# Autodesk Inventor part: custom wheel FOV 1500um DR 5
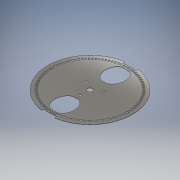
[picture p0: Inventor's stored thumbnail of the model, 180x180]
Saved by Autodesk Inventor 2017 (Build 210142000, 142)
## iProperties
Created: 2016-09
Part Number: custom wheel FOV 1500um DR 5
Material: Generic
Document SubType Name: Modeling
Designer: Radek
Density: 1 g/cm^3
Appearance: Mirror
Author: Radek
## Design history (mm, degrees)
workplane "Work Plane1"
sketch "Sketch1"
  geometry: L1 (-46.781, 4.422)-(-44.253, 4.183) reference; L2 (-44.362, 2.791)-(-46.897, 2.951) reference; L3 (-46.411, 7.351)-(-43.903, 6.954) reference; L4 (-44.099, 5.571)-(-46.619, 5.889) reference; L5 (-45.858, 10.251)-(-43.38, 9.696) reference; L6 (-43.663, 8.329)-(-46.158, 8.805) reference; L7 (-45.124, 13.11)-(-42.685, 12.401) reference; L8 (-43.054, 11.054)-(-45.514, 11.686) reference; L9 (-44.212, 15.917)-(-41.822, 15.057) reference; L10 (-42.274, 13.736)-(-44.69, 14.521) reference; L11 (-43.125, 18.662)-(-40.794, 17.653) reference; L12 (-41.329, 16.363)-(-43.69, 17.298) reference; L13 (-41.868, 21.333)-(-39.605, 20.18) reference; L14 (-40.22, 18.926)-(-42.518, 20.007) reference; L15 (-40.446, 23.92)-(-38.26, 22.627) reference; L16 (-38.952, 21.414)-(-41.178, 22.638) reference; L17 (-38.865, 26.412)-(-36.764, 24.985) reference; L18 (-37.53, 23.818)-(-39.675, 25.179) reference; L19 (-37.129, 28.801)-(-35.122, 27.244) reference; L20 (-35.961, 26.127)-(-38.016, 27.62) reference; L21 (-35.248, 31.075)-(-33.342, 29.395) reference; L22 (-34.249, 28.333)-(-36.206, 29.953) reference; L23 (-33.227, 33.227)-(-31.431, 31.431) reference; L24 (-32.403, 30.428)-(-34.254, 32.167) reference; L25 (-31.075, 35.248)-(-29.395, 33.342) reference; L26 (-30.428, 32.403)-(-32.167, 34.254) reference; L27 (-28.801, 37.129)-(-27.244, 35.122) reference; L28 (-28.333, 34.249)-(-29.953, 36.206) reference; L29 (-26.412, 38.865)-(-24.985, 36.764) reference; L30 (-26.127, 35.961)-(-27.62, 38.016) reference; L31 (-23.92, 40.446)-(-22.627, 38.26) reference; L32 (-23.818, 37.53)-(-25.179, 39.675) reference; L33 (-21.333, 41.868)-(-20.18, 39.605) reference; L34 (-21.414, 38.952)-(-22.638, 41.178) reference; L35 (-18.662, 43.125)-(-17.653, 40.794) reference; L36 (-18.926, 40.22)-(-20.007, 42.518) reference; L37 (-15.917, 44.212)-(-15.057, 41.822) reference; L38 (-16.363, 41.329)-(-17.298, 43.69) reference; L39 (-13.11, 45.124)-(-12.401, 42.685) reference; L40 (-13.736, 42.274)-(-14.521, 44.69) reference; L41 (-10.251, 45.858)-(-9.696, 43.38) reference; L42 (-11.054, 43.054)-(-11.686, 45.514) reference; L43 (-7.351, 46.411)-(-6.954, 43.903) reference; L44 (-8.329, 43.663)-(-8.805, 46.158) reference; L45 (-4.422, 46.781)-(-4.183, 44.253) reference; L46 (-5.571, 44.099)-(-5.889, 46.619) reference; L47 (-1.476, 46.967)-(-1.396, 44.428) reference; L48 (-2.791, 44.362)-(-2.951, 46.897) reference; L49 (1.476, 46.967)-(1.396, 44.428) reference; L50 (0, 44.45)-(0, 46.99) reference; L51 (4.422, 46.781)-(4.183, 44.253) reference; L52 (2.791, 44.362)-(2.951, 46.897) reference; L53 (7.351, 46.411)-(6.954, 43.903) reference; L54 (5.571, 44.099)-(5.889, 46.619) reference; L55 (10.251, 45.858)-(9.696, 43.38) reference; L56 (8.329, 43.663)-(8.805, 46.158) reference; L57 (13.11, 45.124)-(12.401, 42.685) reference; L58 (11.054, 43.054)-(11.686, 45.514) reference; L59 (15.917, 44.212)-(15.057, 41.822) reference; L60 (13.736, 42.274)-(14.521, 44.69) reference; L61 (18.662, 43.125)-(17.653, 40.794) reference; L62 (16.363, 41.329)-(17.298, 43.69) reference; L63 (21.333, 41.868)-(20.18, 39.605) reference; L64 (18.926, 40.22)-(20.007, 42.518) reference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; C1 r 50.8 at (0, 0) reference; C2 r 2.984 at (0, 0) reference; C3 r 1.524 at (0, 6.553) reference; C4 r 1.524 at (10.339, 5.969) reference; C5 r 2.984 at (0, 0) reference; C6 r 1.524 at (0, -11.938) reference; C7 r 1.524 at (-5.675, -3.277) reference; C8 r 1.524 at (-10.339, 5.969) reference; C9 r 1.524 at (5.675, -3.277) reference; C10 r 50.8 at (0, 0) reference; C11 r 1.524 at (-5.675, -3.277) reference; C12 r 1.524 at (-10.339, 5.969) reference; C13 r 1.524 at (0, 6.553) reference; C14 r 1.524 at (10.339, 5.969) reference; C15 r 1.524 at (5.675, -3.277) reference; C16 r 1.524 at (0, -11.938) reference; C17 r 2.984 at (0, 0) reference; A1 r 17.081 centre (0, 0) between (0, -17.081) and (17.081, 0) reference; A2 r 17.081 centre (0, 0) between (0, 17.081) and (-17.081, 0) reference; A3 r 43.18 centre (0, 0) between (0, 43.18) and (-43.18, 0) reference; A4 r 43.18 centre (0, 0) between (0, -43.18) and (43.18, 0) reference; A5 r 44.45 centre (0, 0) between (-44.253, 4.183) and (-44.362, 2.791) reference; A6 r 46.99 centre (0, 0) between (-46.781, 4.422) and (-46.897, 2.951) reference; A7 r 44.45 centre (0, 0) between (-43.903, 6.954) and (-44.099, 5.571) reference; A8 r 46.99 centre (0, 0) between (-46.411, 7.351) and (-46.619, 5.889) reference; A9 r 44.45 centre (0, 0) between (-43.38, 9.696) and (-43.663, 8.329) reference; A10 r 46.99 centre (0, 0) between (-45.858, 10.251) and (-46.158, 8.805) reference; A11 r 44.45 centre (0, 0) between (-42.685, 12.401) and (-43.054, 11.054) reference; A12 r 46.99 centre (0, 0) between (-45.124, 13.11) and (-45.514, 11.686) reference; A13 r 44.45 centre (0, 0) between (-41.822, 15.057) and (-42.274, 13.736) reference; A14 r 46.99 centre (0, 0) between (-44.212, 15.917) and (-44.69, 14.521) reference; A15 r 44.45 centre (0, 0) between (-40.794, 17.653) and (-41.329, 16.363) reference; A16 r 46.99 centre (0, 0) between (-43.125, 18.662) and (-43.69, 17.298) reference; A17 r 44.45 centre (0, 0) between (-39.605, 20.18) and (-40.22, 18.926) reference; A18 r 46.99 centre (0, 0) between (-41.868, 21.333) and (-42.518, 20.007) reference; A19 r 44.45 centre (0, 0) between (-38.26, 22.627) and (-38.952, 21.414) reference; A20 r 46.99 centre (0, 0) between (-40.446, 23.92) and (-41.178, 22.638) reference; A21 r 44.45 centre (0, 0) between (-36.764, 24.985) and (-37.53, 23.818) reference; A22 r 46.99 centre (0, 0) between (-38.865, 26.412) and (-39.675, 25.179) reference; A23 r 44.45 centre (0, 0) between (-35.122, 27.244) and (-35.961, 26.127) reference; A24 r 46.99 centre (0, 0) between (-37.129, 28.801) and (-38.016, 27.62) reference; A25 r 44.45 centre (0, 0) between (-33.342, 29.395) and (-34.249, 28.333) reference; A26 r 46.99 centre (0, 0) between (-35.248, 31.075) and (-36.206, 29.953) reference; A27 r 44.45 centre (0, 0) between (-31.431, 31.431) and (-32.403, 30.428) reference; A28 r 46.99 centre (0, 0) between (-33.227, 33.227) and (-34.254, 32.167) reference; A29 r 44.45 centre (0, 0) between (-29.395, 33.342) and (-30.428, 32.403) reference; A30 r 46.99 centre (0, 0) between (-31.075, 35.248) and (-32.167, 34.254) reference; A31 r 44.45 centre (0, 0) between (-27.244, 35.122) and (-28.333, 34.249) reference; A32 r 46.99 centre (0, 0) between (-28.801, 37.129) and (-29.953, 36.206) reference; A33 r 44.45 centre (0, 0) between (-24.985, 36.764) and (-26.127, 35.961) reference; A34 r 46.99 centre (0, 0) between (-26.412, 38.865) and (-27.62, 38.016) reference; A35 r 44.45 centre (0, 0) between (-22.627, 38.26) and (-23.818, 37.53) reference; A36 r 46.99 centre (0, 0) between (-23.92, 40.446) and (-25.179, 39.675) reference; A37 r 44.45 centre (0, 0) between (-20.18, 39.605) and (-21.414, 38.952) reference; A38 r 46.99 centre (0, 0) between (-21.333, 41.868) and (-22.638, 41.178) reference; A39 r 44.45 centre (0, 0) between (-17.653, 40.794) and (-18.926, 40.22) reference; A40 r 46.99 centre (0, 0) between (-18.662, 43.125) and (-20.007, 42.518) reference; A41 r 44.45 centre (0, 0) between (-15.057, 41.822) and (-16.363, 41.329) reference; A42 r 46.99 centre (0, 0) between (-15.917, 44.212) and (-17.298, 43.69) reference; A43 r 44.45 centre (0, 0) between (-12.401, 42.685) and (-13.736, 42.274) reference; A44 r 46.99 centre (0, 0) between (-13.11, 45.124) and (-14.521, 44.69) reference; A45 r 44.45 centre (0, 0) between (-9.696, 43.38) and (-11.054, 43.054) reference; A46 r 46.99 centre (0, 0) between (-10.251, 45.858) and (-11.686, 45.514) reference; A47 r 44.45 centre (0, 0) between (-6.954, 43.903) and (-8.329, 43.663) reference; A48 r 46.99 centre (0, 0) between (-7.351, 46.411) and (-8.805, 46.158) reference; A49 r 44.45 centre (0, 0) between (-4.183, 44.253) and (-5.571, 44.099) reference; A50 r 46.99 centre (0, 0) between (-4.422, 46.781) and (-5.889, 46.619) reference; A51 r 44.45 centre (0, 0) between (-1.396, 44.428) and (-2.791, 44.362) reference; A52 r 46.99 centre (0, 0) between (-1.476, 46.967) and (-2.951, 46.897) reference; A53 r 44.45 centre (0, 0) between (1.396, 44.428) and (0, 44.45) reference; A54 r 46.99 centre (0, 0) between (1.476, 46.967) and (0, 46.99) reference; A55 r 44.45 centre (0, 0) between (4.183, 44.253) and (2.791, 44.362) reference; A56 r 46.99 centre (0, 0) between (4.422, 46.781) and (2.951, 46.897) reference; A57 r 44.45 centre (0, 0) between (6.954, 43.903) and (5.571, 44.099) reference; A58 r 46.99 centre (0, 0) between (7.351, 46.411) and (5.889, 46.619) reference; A59 r 44.45 centre (0, 0) between (9.696, 43.38) and (8.329, 43.663) reference; A60 r 46.99 centre (0, 0) between (10.251, 45.858) and (8.805, 46.158) reference; A61 r 44.45 centre (0, 0) between (12.401, 42.685) and (11.054, 43.054) reference; A62 r 46.99 centre (0, 0) between (13.11, 45.124) and (11.686, 45.514) reference; A63 r 44.45 centre (0, 0) between (15.057, 41.822) and (13.736, 42.274) reference; A64 r 46.99 centre (0, 0) between (15.917, 44.212) and (14.521, 44.69) reference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; 1 further point
  constraints: 8 end point, 2 collinear, 1 parallel
extrude "Extrusion2" new body sketch "Sketch1" distance "d2" = 0.3; taper "d3" = 0 deg
sketch "Sketch2"
  geometry: L1 (-46.781, 4.422)-(-44.253, 4.183) reference; L2 (-44.362, 2.791)-(-46.897, 2.951) reference; L3 (-46.411, 7.351)-(-43.903, 6.954) reference; L4 (-44.099, 5.571)-(-46.619, 5.889) reference; L5 (-45.858, 10.251)-(-43.38, 9.696) reference; L6 (-43.663, 8.329)-(-46.158, 8.805) reference; L7 (-45.124, 13.11)-(-42.685, 12.401) reference; L8 (-43.054, 11.054)-(-45.514, 11.686) reference; L9 (-44.212, 15.917)-(-41.822, 15.057) reference; L10 (-42.274, 13.736)-(-44.69, 14.521) reference; L11 (-43.125, 18.662)-(-40.794, 17.653) reference; L12 (-41.329, 16.363)-(-43.69, 17.298) reference; L13 (-41.868, 21.333)-(-39.605, 20.18) reference; L14 (-40.22, 18.926)-(-42.518, 20.007) reference; L15 (-40.446, 23.92)-(-38.26, 22.627) reference; L16 (-38.952, 21.414)-(-41.178, 22.638) reference; L17 (-38.865, 26.412)-(-36.764, 24.985) reference; L18 (-37.53, 23.818)-(-39.675, 25.179) reference; L19 (-37.129, 28.801)-(-35.122, 27.244) reference; L20 (-35.961, 26.127)-(-38.016, 27.62) reference; L21 (-35.248, 31.075)-(-33.342, 29.395) reference; L22 (-34.249, 28.333)-(-36.206, 29.953) reference; L23 (-33.227, 33.227)-(-31.431, 31.431) reference; L24 (-32.403, 30.428)-(-34.254, 32.167) reference; L25 (-31.075, 35.248)-(-29.395, 33.342) reference; L26 (-30.428, 32.403)-(-32.167, 34.254) reference; L27 (-28.801, 37.129)-(-27.244, 35.122) reference; L28 (-28.333, 34.249)-(-29.953, 36.206) reference; L29 (-26.412, 38.865)-(-24.985, 36.764) reference; L30 (-26.127, 35.961)-(-27.62, 38.016) reference; L31 (-23.92, 40.446)-(-22.627, 38.26) reference; L32 (-23.818, 37.53)-(-25.179, 39.675) reference; L33 (-21.333, 41.868)-(-20.18, 39.605) reference; L34 (-21.414, 38.952)-(-22.638, 41.178) reference; L35 (-18.662, 43.125)-(-17.653, 40.794) reference; L36 (-18.926, 40.22)-(-20.007, 42.518) reference; L37 (-15.917, 44.212)-(-15.057, 41.822) reference; L38 (-16.363, 41.329)-(-17.298, 43.69) reference; L39 (-13.11, 45.124)-(-12.401, 42.685) reference; L40 (-13.736, 42.274)-(-14.521, 44.69) reference; L41 (-10.251, 45.858)-(-9.696, 43.38) reference; L42 (-11.054, 43.054)-(-11.686, 45.514) reference; L43 (-7.351, 46.411)-(-6.954, 43.903) reference; L44 (-8.329, 43.663)-(-8.805, 46.158) reference; L45 (-4.422, 46.781)-(-4.183, 44.253) reference; L46 (-5.571, 44.099)-(-5.889, 46.619) reference; L47 (-1.476, 46.967)-(-1.396, 44.428) reference; L48 (-2.791, 44.362)-(-2.951, 46.897) reference; L49 (1.476, 46.967)-(1.396, 44.428) reference; L50 (0, 44.45)-(0, 46.99) reference; L51 (4.422, 46.781)-(4.183, 44.253) reference; L52 (2.791, 44.362)-(2.951, 46.897) reference; L53 (7.351, 46.411)-(6.954, 43.903) reference; L54 (5.571, 44.099)-(5.889, 46.619) reference; L55 (10.251, 45.858)-(9.696, 43.38) reference; L56 (8.329, 43.663)-(8.805, 46.158) reference; L57 (13.11, 45.124)-(12.401, 42.685) reference; L58 (11.054, 43.054)-(11.686, 45.514) reference; L59 (15.917, 44.212)-(15.057, 41.822) reference; L60 (13.736, 42.274)-(14.521, 44.69) reference; L61 (18.662, 43.125)-(17.653, 40.794) reference; L62 (16.363, 41.329)-(17.298, 43.69) reference; L63 (21.333, 41.868)-(20.18, 39.605) reference; L64 (18.926, 40.22)-(20.007, 42.518) reference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; C1 r 50.8 at (0, 0) reference; C2 r 1.524 at (-5.675, -3.277) reference; C3 r 1.524 at (-10.339, 5.969) reference; C4 r 1.524 at (0, 6.553) reference; C5 r 1.524 at (10.339, 5.969) reference; C6 r 1.524 at (5.675, -3.277) reference; C7 r 1.524 at (0, -11.938) reference; C8 r 2.984 at (0, 0) reference; A1 r 44.45 centre (0, 0) between (-44.253, 4.183) and (-44.362, 2.791) reference; A2 r 46.99 centre (0, 0) between (-46.781, 4.422) and (-46.897, 2.951) reference; A3 r 44.45 centre (0, 0) between (-43.903, 6.954) and (-44.099, 5.571) reference; A4 r 46.99 centre (0, 0) between (-46.411, 7.351) and (-46.619, 5.889) reference; A5 r 44.45 centre (0, 0) between (-43.38, 9.696) and (-43.663, 8.329) reference; A6 r 46.99 centre (0, 0) between (-45.858, 10.251) and (-46.158, 8.805) reference; A7 r 44.45 centre (0, 0) between (-42.685, 12.401) and (-43.054, 11.054) reference; A8 r 46.99 centre (0, 0) between (-45.124, 13.11) and (-45.514, 11.686) reference; A9 r 44.45 centre (0, 0) between (-41.822, 15.057) and (-42.274, 13.736) reference; A10 r 46.99 centre (0, 0) between (-44.212, 15.917) and (-44.69, 14.521) reference; A11 r 44.45 centre (0, 0) between (-40.794, 17.653) and (-41.329, 16.363) reference; A12 r 46.99 centre (0, 0) between (-43.125, 18.662) and (-43.69, 17.298) reference; A13 r 44.45 centre (0, 0) between (-39.605, 20.18) and (-40.22, 18.926) reference; A14 r 46.99 centre (0, 0) between (-41.868, 21.333) and (-42.518, 20.007) reference; A15 r 44.45 centre (0, 0) between (-38.26, 22.627) and (-38.952, 21.414) reference; A16 r 46.99 centre (0, 0) between (-40.446, 23.92) and (-41.178, 22.638) reference; A17 r 44.45 centre (0, 0) between (-36.764, 24.985) and (-37.53, 23.818) reference; A18 r 46.99 centre (0, 0) between (-38.865, 26.412) and (-39.675, 25.179) reference; A19 r 44.45 centre (0, 0) between (-35.122, 27.244) and (-35.961, 26.127) reference; A20 r 46.99 centre (0, 0) between (-37.129, 28.801) and (-38.016, 27.62) reference; A21 r 44.45 centre (0, 0) between (-33.342, 29.395) and (-34.249, 28.333) reference; A22 r 46.99 centre (0, 0) between (-35.248, 31.075) and (-36.206, 29.953) reference; A23 r 44.45 centre (0, 0) between (-31.431, 31.431) and (-32.403, 30.428) reference; A24 r 46.99 centre (0, 0) between (-33.227, 33.227) and (-34.254, 32.167) reference; A25 r 44.45 centre (0, 0) between (-29.395, 33.342) and (-30.428, 32.403) reference; A26 r 46.99 centre (0, 0) between (-31.075, 35.248) and (-32.167, 34.254) reference; A27 r 44.45 centre (0, 0) between (-27.244, 35.122) and (-28.333, 34.249) reference; A28 r 46.99 centre (0, 0) between (-28.801, 37.129) and (-29.953, 36.206) reference; A29 r 44.45 centre (0, 0) between (-24.985, 36.764) and (-26.127, 35.961) reference; A30 r 46.99 centre (0, 0) between (-26.412, 38.865) and (-27.62, 38.016) reference; A31 r 44.45 centre (0, 0) between (-22.627, 38.26) and (-23.818, 37.53) reference; A32 r 46.99 centre (0, 0) between (-23.92, 40.446) and (-25.179, 39.675) reference; A33 r 44.45 centre (0, 0) between (-20.18, 39.605) and (-21.414, 38.952) reference; A34 r 46.99 centre (0, 0) between (-21.333, 41.868) and (-22.638, 41.178) reference; A35 r 44.45 centre (0, 0) between (-17.653, 40.794) and (-18.926, 40.22) reference; A36 r 46.99 centre (0, 0) between (-18.662, 43.125) and (-20.007, 42.518) reference; A37 r 44.45 centre (0, 0) between (-15.057, 41.822) and (-16.363, 41.329) reference; A38 r 46.99 centre (0, 0) between (-15.917, 44.212) and (-17.298, 43.69) reference; A39 r 44.45 centre (0, 0) between (-12.401, 42.685) and (-13.736, 42.274) reference; A40 r 46.99 centre (0, 0) between (-13.11, 45.124) and (-14.521, 44.69) reference; A41 r 44.45 centre (0, 0) between (-9.696, 43.38) and (-11.054, 43.054) reference; A42 r 46.99 centre (0, 0) between (-10.251, 45.858) and (-11.686, 45.514) reference; A43 r 44.45 centre (0, 0) between (-6.954, 43.903) and (-8.329, 43.663) reference; A44 r 46.99 centre (0, 0) between (-7.351, 46.411) and (-8.805, 46.158) reference; A45 r 44.45 centre (0, 0) between (-4.183, 44.253) and (-5.571, 44.099) reference; A46 r 46.99 centre (0, 0) between (-4.422, 46.781) and (-5.889, 46.619) reference; A47 r 44.45 centre (0, 0) between (-1.396, 44.428) and (-2.791, 44.362) reference; A48 r 46.99 centre (0, 0) between (-1.476, 46.967) and (-2.951, 46.897) reference; A49 r 44.45 centre (0, 0) between (1.396, 44.428) and (0, 44.45) reference; A50 r 46.99 centre (0, 0) between (1.476, 46.967) and (0, 46.99) reference; A51 r 44.45 centre (0, 0) between (4.183, 44.253) and (2.791, 44.362) reference; A52 r 46.99 centre (0, 0) between (4.422, 46.781) and (2.951, 46.897) reference; A53 r 44.45 centre (0, 0) between (6.954, 43.903) and (5.571, 44.099) reference; A54 r 46.99 centre (0, 0) between (7.351, 46.411) and (5.889, 46.619) reference; A55 r 44.45 centre (0, 0) between (9.696, 43.38) and (8.329, 43.663) reference; A56 r 46.99 centre (0, 0) between (10.251, 45.858) and (8.805, 46.158) reference; A57 r 44.45 centre (0, 0) between (12.401, 42.685) and (11.054, 43.054) reference; A58 r 46.99 centre (0, 0) between (13.11, 45.124) and (11.686, 45.514) reference; A59 r 44.45 centre (0, 0) between (15.057, 41.822) and (13.736, 42.274) reference; A60 r 46.99 centre (0, 0) between (15.917, 44.212) and (14.521, 44.69) reference; A61 r 44.45 centre (0, 0) between (17.653, 40.794) and (16.363, 41.329) reference; A62 r 46.99 centre (0, 0) between (18.662, 43.125) and (17.298, 43.69) reference; A63 r 44.45 centre (0, 0) between (20.18, 39.605) and (18.926, 40.22) reference; A64 r 46.99 centre (0, 0) between (21.333, 41.868) and (20.007, 42.518) reference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; 1 further point
  constraints: 8 end point, 1 collinear
extrude "Extrusion3" cut sketch "Sketch2" stored distance "d4" = 0.254; taper "d5" = 0 deg
sketch "Sketch3" dims "d20" = 9.26667 (= 0.5 x holediameter), "d21" = 13.10505 (= 1.41421 x d20)
  geometry: L1 (-10.339, 5.969)-(10.339, 5.969); L2 (0, 0)-(50.8, 0); L3 (0, 44.45)-(0, 46.99) reference; L4 (0, 0)-(0, 50.8); L5 (0, 30)-(0, 16.895); L6 (0, 50.165)-(0, 48.26) reference; L7 (-48.26, 0)-(-50.165, 0) reference; L8 (0, 0)-(13.619, 31.718); L9 (0, 50.8)-(0, 50.165); L10 (1.263, 16.848)-(3.221, 42.985); L11 (-1.263, 16.848)-(-3.221, 42.985); C1 r 2.984 at (0, 0) reference; C2 r 15.25 at (0, 0); C3 r 1.524 at (-10.339, 5.969) reference; C4 r 1.524 at (0, -11.938) reference; C5 r 1.524 at (10.339, 5.969) reference; C6 r 1.524 at (-5.675, -3.277) reference; C7 r 1.524 at (5.675, -3.277) reference; A1 r 50.8 centre (0, 0) between (50.8, 0) and (0, 50.8) reference; A2 r 48.26 centre (0, 0) between (0, 48.26) and (-48.26, 0) reference; A3 r 50.165 centre (0, 0) between (0, 50.165) and (-50.165, 0) reference; A4 r 50.165 centre (0, 0) between (-20.154, -45.939) and (22.037, -45.066); A5 r 48.26 centre (0, 0) between (-19.033, -44.348) and (20.956, -43.472); 3 further points; 3 other entities
  constraints: 16 end point, 8 point on circle, 3 centre point, 3 coincident, 2 midpoint, 2 vertical, 1 collinear, 1 horizontal, 1 parallel, 1 point on line, 1 vertical alignment, 19 other
  dimensions: "d9" = 30.5 diameter of C2; "d18" = 0 distance between parallel lines of L4 L5; "d19" = 30 distance of point (0, 0) L5.start (= offaxis); "d24" = 0.748 dimension on point (0, 0) L5.start point (-2.242, 29.916) (= 0.5 x angle); "d28" = 0.748 dimension on point (0, 0) point (2.242, 29.916) L5.start (= 0.5 x angle); "d32" = 0.635 distance of L4.end L6.start (derived)
extrude "Extrusion7" cut sketch "Sketch3" stored distance "d40" = 10; taper "d41" = 0 deg
sketch "Sketch4"
  geometry: L1 (-3.221, 42.985)-(-1.263, 16.848) reference; L2 (1.263, 16.848)-(3.221, 42.985) reference; L3 (3.221, 42.985)-(1.263, 16.848) reference; L4 (-1.263, 16.848)-(-3.221, 42.985) reference; L5 (-1.263, 16.848)-(-3.221, 42.985); L6 (1.263, 16.848)-(3.221, 42.985); C1 r 2.984 at (0, 0) reference; C2 r 50.8 at (0, 0) reference; A1 r 16.895 centre (0, 0) between (1.263, 16.848) and (-1.263, 16.848); A2 r 43.105 centre (0, 0) between (3.221, 42.985) and (-3.221, 42.985); 3 further points; 2 other entities
  constraints: 4 end point, 4 point on circle, 2 centre point, 2 coincident, 2 collinear, 2 other
extrude "Extrusion8" cut sketch "Sketch4" stored distance "d42" = 10; taper "d43" = 0 deg
sketch "Sketch5"
  geometry: L1 (0, 0)-(-7.947, 50.175); L2 (0, 0)-(7.947, 50.175); L3 (7.524, 47.508)-(7.837, 49.483); L4 (-7.524, 47.508)-(-7.837, 49.483); L5 (6.954, 43.903)-(7.351, 46.411) reference; L6 (4.422, 46.781)-(4.183, 44.253) reference; L7 (7.351, 46.411)-(6.954, 43.903) reference; C1 r 2.984 at (0, 0) reference; A1 r 50.8 centre (0, 0) between (-7.947, 50.175) and (7.947, 50.175) reference; A2 r 16.895 centre (0, 0) between (1.263, 16.848) and (-1.263, 16.848) reference; A3 r 43.105 centre (0, 0) between (3.221, 42.985) and (-3.221, 42.985) reference; A4 r 48.1 centre (0, 0) between (7.524, 47.508) and (-7.524, 47.508); A5 r 50.1 centre (0, 0) between (7.837, 49.483) and (-7.837, 49.483); 4 further points; 2 other entities
  constraints: 8 end point, 6 point on circle, 3 point on line, 2 centre point, 2 coincident, 2 collinear, 1 midpoint, 8 other
  dimensions: "d44" = 0.7 radial gap between concentric circles of A1 A5; "d45" = 2 radial gap between concentric circles of A5 A4; "d53" = 18 deg angle of L1 L2
extrude "Extrusion9" cut sketch "Sketch5" stored distance "d46" = 10; taper "d47" = 0 deg
pattern_circular "Circular Pattern3" dims angle "d49" = 360 deg
sketch "Sketch6"
  geometry: L1 (16.895, 0)-(16.848, 0) reference; L2 (42.985, 0)-(43.105, 0) reference; L3 (16.848, -0.3)-(16.895, -0.3) reference; L4 (43.105, -0.3)-(42.985, -0.3) reference; L5 (-50.8, 0)-(50.8, 0) reference; L6 (-50.8, -0.3)-(50.8, -0.3) reference; L7 (16.895, 0)-(43.105, 0); L8 (16.895, -0.3)-(43.105, -0.3); L9 (30, -0.3)-(30, 0); L10 (30, -0.15)-(32.935, -3.085); 1 further point
  constraints: 8 end point, 3 midpoint, 1 collinear, 1 parallel
  dimensions: "d51" = 135 deg angle of L10 L9
workaxis "Work Axis1"
workplane "Work Plane3"
  workplane "Work Plane2"
sketch "Sketch7"
  geometry: L1 (0, -11.938)-(-10.339, 5.969); C1 r 1.524 at (0, -11.938) reference; C2 r 1.524 at (-10.339, 5.969) reference; C3 r 2.984 at (0, 0) reference; C4 r 10.414 at (0, 0); 2 further points
  constraints: 2 end point, 1 centre point, 1 coincident, 1 tangent, 1 other
extrude "Extrusion11" cut sketch "Sketch7" stored distance "d57" = 10; taper "d58" = 0 deg
sketch "Sketch8"
  geometry: L1 (7.524, -47.508)-(7.837, -49.483) reference; L2 (-7.837, -49.483)-(-7.524, -47.508) reference; L3 (7.837, 49.483)-(7.524, 47.508) reference; L4 (-7.524, 47.508)-(-7.837, 49.483) reference; L5 (-46.967, -1.476)-(-44.428, -1.396) reference; L6 (-44.428, -1.396)-(-44.362, -2.791) reference; L7 (-44.362, -2.791)-(-46.897, -2.951) reference; L8 (-46.897, -2.951)-(-46.967, -1.476) reference; L9 (-46.781, -4.422)-(-44.253, -4.183) reference; L10 (-44.253, -4.183)-(-44.099, -5.571) reference; L11 (-44.099, -5.571)-(-46.619, -5.889) reference; L12 (-46.619, -5.889)-(-46.781, -4.422) reference; L13 (-46.411, -7.351)-(-43.903, -6.954) reference; L14 (-43.903, -6.954)-(-43.663, -8.329) reference; L15 (-43.663, -8.329)-(-46.158, -8.805) reference; L16 (-46.158, -8.805)-(-46.411, -7.351) reference; L17 (-45.858, -10.251)-(-43.38, -9.696) reference; L18 (-43.38, -9.696)-(-43.054, -11.054) reference; L19 (-43.054, -11.054)-(-45.514, -11.686) reference; L20 (-45.514, -11.686)-(-45.858, -10.251) reference; L21 (-45.124, -13.11)-(-42.685, -12.401) reference; L22 (-42.685, -12.401)-(-42.274, -13.736) reference; L23 (-42.274, -13.736)-(-44.69, -14.521) reference; L24 (-44.69, -14.521)-(-45.124, -13.11) reference; L25 (-44.212, -15.917)-(-41.822, -15.057) reference; L26 (-41.822, -15.057)-(-41.329, -16.363) reference; L27 (-41.329, -16.363)-(-43.69, -17.298) reference; L28 (-43.69, -17.298)-(-44.212, -15.917) reference; L29 (-43.125, -18.662)-(-40.794, -17.653) reference; L30 (-40.794, -17.653)-(-40.22, -18.926) reference; L31 (-40.22, -18.926)-(-42.518, -20.007) reference; L32 (-42.518, -20.007)-(-43.125, -18.662) reference; L33 (-41.868, -21.333)-(-39.605, -20.18) reference; L34 (-39.605, -20.18)-(-38.952, -21.414) reference; L35 (-38.952, -21.414)-(-41.178, -22.638) reference; L36 (-41.178, -22.638)-(-41.868, -21.333) reference; L37 (-40.446, -23.92)-(-38.26, -22.627) reference; L38 (-38.26, -22.627)-(-37.53, -23.818) reference; L39 (-37.53, -23.818)-(-39.675, -25.179) reference; L40 (-39.675, -25.179)-(-40.446, -23.92) reference; L41 (-38.865, -26.412)-(-36.764, -24.985) reference; L42 (-36.764, -24.985)-(-35.961, -26.127) reference; L43 (-35.961, -26.127)-(-38.016, -27.62) reference; L44 (-38.016, -27.62)-(-38.865, -26.412) reference; L45 (-37.129, -28.801)-(-35.122, -27.244) reference; L46 (-35.122, -27.244)-(-34.249, -28.333) reference; L47 (-34.249, -28.333)-(-36.206, -29.953) reference; L48 (-36.206, -29.953)-(-37.129, -28.801) reference; L49 (-35.248, -31.075)-(-33.342, -29.395) reference; L50 (-33.342, -29.395)-(-32.403, -30.428) reference; L51 (-32.403, -30.428)-(-34.254, -32.167) reference; L52 (-34.254, -32.167)-(-35.248, -31.075) reference; L53 (-33.227, -33.227)-(-31.431, -31.431) reference; L54 (-31.431, -31.431)-(-30.428, -32.403) reference; L55 (-30.428, -32.403)-(-32.167, -34.254) reference; L56 (-32.167, -34.254)-(-33.227, -33.227) reference; L57 (-31.075, -35.248)-(-29.395, -33.342) reference; L58 (-29.395, -33.342)-(-28.333, -34.249) reference; L59 (-28.333, -34.249)-(-29.953, -36.206) reference; L60 (-29.953, -36.206)-(-31.075, -35.248) reference; L61 (-28.801, -37.129)-(-27.244, -35.122) reference; L62 (-27.244, -35.122)-(-26.127, -35.961) reference; L63 (-26.127, -35.961)-(-27.62, -38.016) reference; L64 (-27.62, -38.016)-(-28.801, -37.129) reference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; C1 r 2.984 at (0, 0) reference; C2 r 1.524 at (5.675, -3.277) reference; C3 r 1.524 at (-10.339, 5.969) reference; C4 r 1.524 at (-5.675, -3.277) reference; C5 r 1.524 at (0, -11.938) reference; C6 r 1.524 at (10.339, 5.969) reference; C7 r 1.524 at (0, 6.553) reference; C8 r 50.8 at (0, 0) reference; C9 r 2.984 at (0, 0) reference; A1 r 16.895 centre (0, 0) between (-1.263, -16.848) and (1.263, -16.848) reference; A2 r 43.105 centre (0, 0) between (-3.221, -42.985) and (3.221, -42.985) reference; A3 r 50.1 centre (0, 0) between (-7.837, -49.483) and (7.837, -49.483) reference; A4 r 48.1 centre (0, 0) between (-7.524, -47.508) and (7.524, -47.508) reference; A5 r 48.1 centre (0, 0) between (7.524, 47.508) and (-7.524, 47.508) reference; A6 r 50.1 centre (0, 0) between (7.837, 49.483) and (-7.837, 49.483) reference; A7 r 43.105 centre (0, 0) between (3.221, 42.985) and (-3.221, 42.985) reference; A8 r 16.895 centre (0, 0) between (1.263, 16.848) and (-1.263, 16.848) reference; A9 r 43.105 centre (0, 0) between (-3.221, -42.985) and (3.221, -42.985); A10 r 16.895 centre (0, 0) between (-1.263, -16.848) and (1.263, -16.848); 4 further points; 5 other entities
  constraints: 8 end point, 4 point on circle, 2 centre point, 2 coincident, 2 collinear, 2 point on line, 6 other
extrude "Extrusion12" cut sketch "Sketch8" stored distance "d59" = 10; taper "d60" = 0 deg
pattern_circular "Circular Pattern4" dims angle "d62" = 360 deg
sketch "Sketch9"
  geometry: L1 (-44.45, 0)-(-46.99, 0) reference; L2 (-46.99, 0)-(-46.967, 1.476) reference; L3 (-46.967, 1.476)-(-44.428, 1.396) reference; L4 (-44.428, 1.396)-(-44.45, 0) reference; L5 (-46.781, 4.422)-(-44.253, 4.183) reference; L6 (-44.253, 4.183)-(-44.362, 2.791) reference; L7 (-44.362, 2.791)-(-46.897, 2.951) reference; L8 (-46.897, 2.951)-(-46.781, 4.422) reference; L9 (-46.411, 7.351)-(-43.903, 6.954) reference; L10 (-43.903, 6.954)-(-44.099, 5.571) reference; L11 (-44.099, 5.571)-(-46.619, 5.889) reference; L12 (-46.619, 5.889)-(-46.411, 7.351) reference; L13 (-45.858, 10.251)-(-43.38, 9.696) reference; L14 (-43.38, 9.696)-(-43.663, 8.329) reference; L15 (-43.663, 8.329)-(-46.158, 8.805) reference; L16 (-46.158, 8.805)-(-45.858, 10.251) reference; L17 (-45.124, 13.11)-(-42.685, 12.401) reference; L18 (-42.685, 12.401)-(-43.054, 11.054) reference; L19 (-43.054, 11.054)-(-45.514, 11.686) reference; L20 (-45.514, 11.686)-(-45.124, 13.11) reference; L21 (-44.212, 15.917)-(-41.822, 15.057) reference; L22 (-41.822, 15.057)-(-42.274, 13.736) reference; L23 (-42.274, 13.736)-(-44.69, 14.521) reference; L24 (-44.69, 14.521)-(-44.212, 15.917) reference; L25 (-43.125, 18.662)-(-40.794, 17.653) reference; L26 (-40.794, 17.653)-(-41.329, 16.363) reference; L27 (-41.329, 16.363)-(-43.69, 17.298) reference; L28 (-43.69, 17.298)-(-43.125, 18.662) reference; L29 (-41.868, 21.333)-(-39.605, 20.18) reference; L30 (-39.605, 20.18)-(-40.22, 18.926) reference; L31 (-40.22, 18.926)-(-42.518, 20.007) reference; L32 (-42.518, 20.007)-(-41.868, 21.333) reference; L33 (-40.446, 23.92)-(-38.26, 22.627) reference; L34 (-38.26, 22.627)-(-38.952, 21.414) reference; L35 (-38.952, 21.414)-(-41.178, 22.638) reference; L36 (-41.178, 22.638)-(-40.446, 23.92) reference; L37 (-38.865, 26.412)-(-36.764, 24.985) reference; L38 (-36.764, 24.985)-(-37.53, 23.818) reference; L39 (-37.53, 23.818)-(-39.675, 25.179) reference; L40 (-39.675, 25.179)-(-38.865, 26.412) reference; L41 (-37.129, 28.801)-(-35.122, 27.244) reference; L42 (-35.122, 27.244)-(-35.961, 26.127) reference; L43 (-35.961, 26.127)-(-38.016, 27.62) reference; L44 (-38.016, 27.62)-(-37.129, 28.801) reference; L45 (-35.248, 31.075)-(-33.342, 29.395) reference; L46 (-33.342, 29.395)-(-34.249, 28.333) reference; L47 (-34.249, 28.333)-(-36.206, 29.953) reference; L48 (-36.206, 29.953)-(-35.248, 31.075) reference; L49 (-33.227, 33.227)-(-31.431, 31.431) reference; L50 (-31.431, 31.431)-(-32.403, 30.428) reference; L51 (-32.403, 30.428)-(-34.254, 32.167) reference; L52 (-34.254, 32.167)-(-33.227, 33.227) reference; L53 (-31.075, 35.248)-(-29.395, 33.342) reference; L54 (-29.395, 33.342)-(-30.428, 32.403) reference; L55 (-30.428, 32.403)-(-32.167, 34.254) reference; L56 (-32.167, 34.254)-(-31.075, 35.248) reference; L57 (-28.801, 37.129)-(-27.244, 35.122) reference; L58 (-27.244, 35.122)-(-28.333, 34.249) reference; L59 (-28.333, 34.249)-(-29.953, 36.206) reference; L60 (-29.953, 36.206)-(-28.801, 37.129) reference; L61 (-26.412, 38.865)-(-24.985, 36.764) reference; L62 (-24.985, 36.764)-(-26.127, 35.961) reference; L63 (-26.127, 35.961)-(-27.62, 38.016) reference; L64 (-27.62, 38.016)-(-26.412, 38.865) reference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; C1 r 50.8 at (0, 0) reference; C2 r 1.524 at (0, 6.553) reference; C3 r 1.524 at (10.339, 5.969) reference; C4 r 1.524 at (0, -11.938) reference; C5 r 1.524 at (-5.675, -3.277) reference; C6 r 1.524 at (-10.339, 5.969) reference; C7 r 1.524 at (5.675, -3.277) reference; C8 r 2.984 at (0, 0) reference; C9 r 2.984 at (0, 0) reference; A1 r 16.895 centre (0, 0) between (1.263, 16.848) and (-1.263, 16.848) reference; A2 r 48.1 centre (0, 0) between (7.524, 47.508) and (-7.524, 47.508) reference; A3 r 50.1 centre (0, 0) between (7.837, 49.483) and (-7.837, 49.483) reference; A4 r 50.1 centre (0, 0) between (-7.837, -49.483) and (7.837, -49.483) reference; A5 r 48.1 centre (0, 0) between (-7.524, -47.508) and (7.524, -47.508) reference; A6 r 43.105 centre (0, 0) between (-3.221, -42.985) and (3.221, -42.985) reference; A7 r 16.895 centre (0, 0) between (-1.263, -16.848) and (1.263, -16.848) reference; A8 r 48.1 centre (0, 0) between (-7.524, -47.508) and (7.524, -47.508); A9 r 55.8 centre (0, 0) between (-8.729, -55.113) and (8.729, -55.113); A10 r 43.105 centre (0, 0) between (3.221, 42.985) and (-3.221, 42.985) reference; 5 further points; 4 other entities
  constraints: 8 end point, 4 point on circle, 4 point on line, 2 centre point, 2 coincident, 2 collinear, 4 other
  dimensions: "d64" = 5 radial gap between concentric circles of C1 A9
extrude "Extrusion13" cut sketch "Sketch9" stored distance "d65" = 10; taper "d66" = 0 deg
pattern_circular "Circular Pattern5" dims angle "d68" = 360 deg
fillet "Fillet1" dims "d70" = 0.5 (derived)
fillet "Fillet3" dims "d72" = 0.5 (derived)
pattern_circular "Circular Pattern7" dims angle "d77" = 360 deg
sketch "Sketch10"
  geometry: C1 r 1.524 at (-5.675, -3.277) reference; C2 r 1.524 at (0, 6.553) reference; C3 r 1.524 at (5.675, -3.277) reference; 1 further point
extrude "Extrusion14" join sketch "Sketch10" stored distance "d79" = 10; taper "d80" = 0 deg
body "Solid2"
pattern_circular "Circular Pattern1" dims angle "d7" = 360 deg
pattern_circular "Circular Pattern6" dims angle "d74" = 360 deg
node "Reference1"
node "Reference2"
node "Reference3"
node "Reference4"
node "Reference5"
node "Reference6"
node "Reference7"
node "Reference8"
node "Reference9"
node "Reference10"
node "Reference11"
node "Reference12"
node "Reference13"
node "Reference14"
node "Reference15"
node "Reference16"
node "Reference17"
node "Reference18"
node "Reference19"
node "Projected Loop1"
node "Projected Loop2"
other parameters: "d12" = 9.66667 (computed from ftube, FOV), "FOV" = 1.5 [user parameter; used in 2 equation terms], "dutycycle" = 2.44264 (computed from holelength, offaxis) [user parameter], "offaxis" = 30 [user parameter; used in 4 equation terms], "angle" = 1.496 (computed from holediameter, holelength, offaxis) [user parameter; used in 2 equation terms], "holelength" = 23.02132 (computed from dutyratio, offaxis, holediameter) [user parameter; used in 2 equation terms], "holediameter" = 18.53333 (computed from FOV, ftube) [user parameter; used in 3 equation terms], "dutyratio" = 0.5 [user parameter; used in 1 equation term], "d52" = 45 deg, "minradius" = 0.5 [user parameter]
